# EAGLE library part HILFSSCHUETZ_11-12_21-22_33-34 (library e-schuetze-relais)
Hilfsschütz mit zwei 2 Öffnern, 1 Schließer
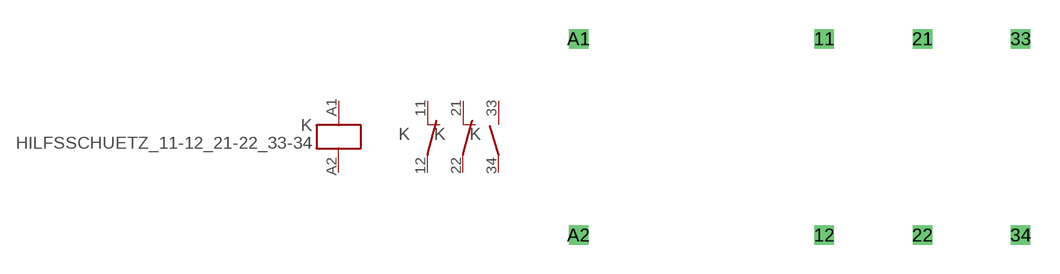
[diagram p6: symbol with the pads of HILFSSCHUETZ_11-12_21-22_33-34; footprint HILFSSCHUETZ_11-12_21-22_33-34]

Designator prefix K; gates G$1=SPULE 3=SCHLIESSER 1=OEFFNER 2=OEFFNER

## HILFSSCHUETZ_11-12_21-22_33-34  [HILFSSCHUETZ_11-12_21-22_33-34]
11  1:1  pas
12  1:2  pas
21  2:1  pas
22  2:2  pas
33  3:3  pas
34  3:4  pas
A1  G$1:A1  in
A2  G$1:A2  in

## Footprint HILFSSCHUETZ_11-12_21-22_33-34 (pad centres in mm)
Dummy
drill 0.5 pad 1 square: 11 2.54,5.08; 12 2.54,-5.08; 21 7.62,5.08; 22 7.62,-5.08; 33 12.7,5.08; 34 12.7,-5.08; A1 -10.16,5.08; A2 -10.16,-5.08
